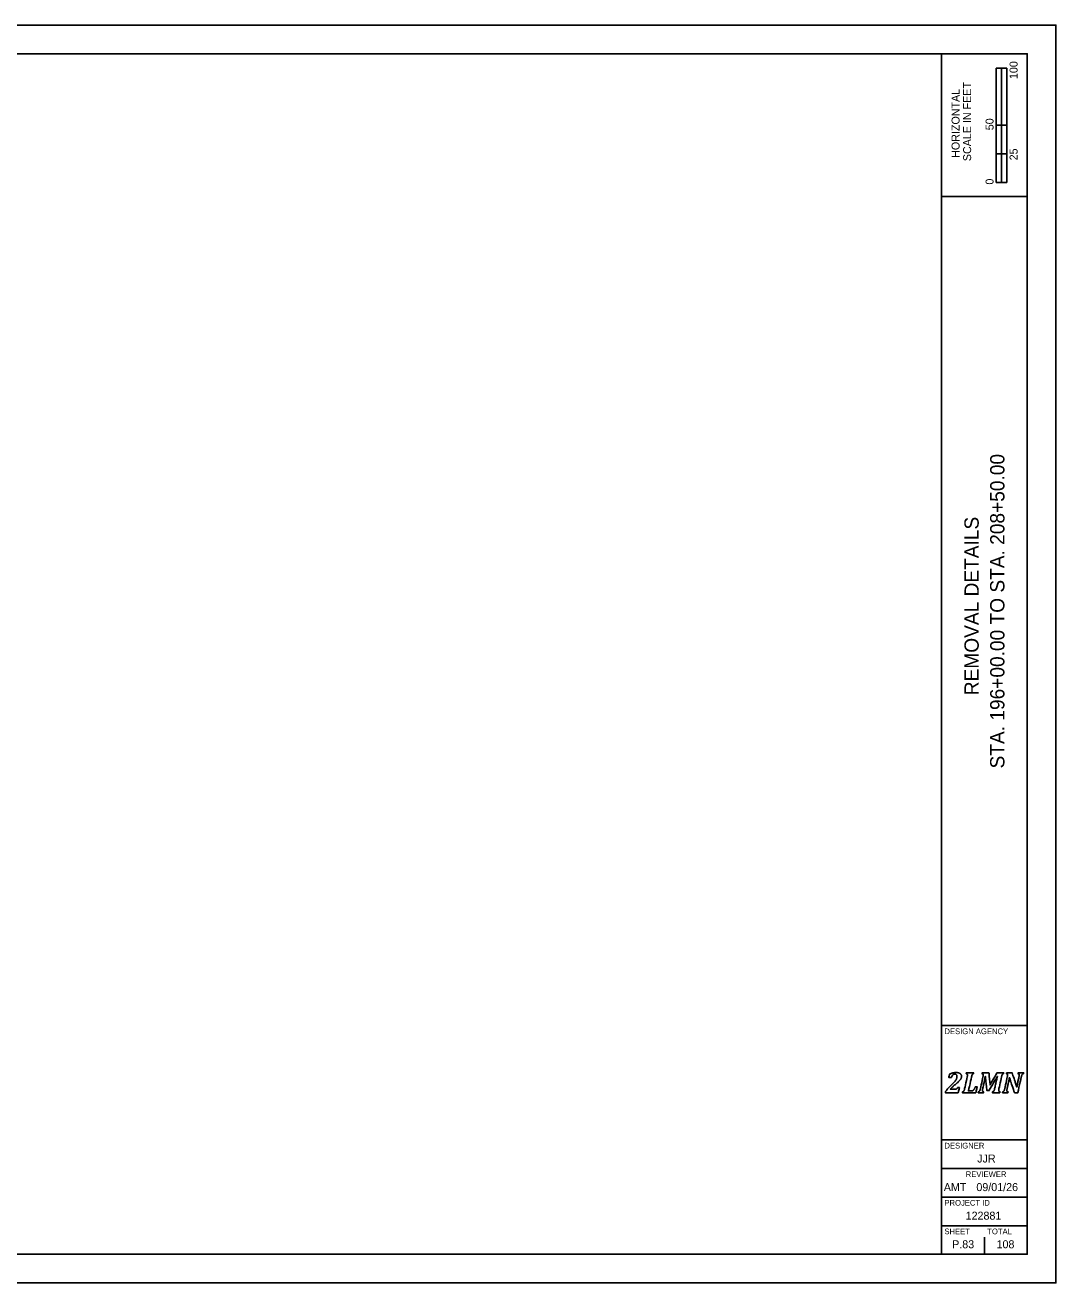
# Model space of a CAD drawing. Extents: x -2.1 to 34, y 0 to 22.
# Drawn here: x 15.96 to 34, y 0 to 22 of the extents above; entities that cross this region are included whole.
import ezdxf

# ---------------------------------------------------------------- set-up
doc = ezdxf.new("R2010")
doc.units = 0
for name, color, linetype in [('SH_Border', 7, 'Continuous'), ('SH_Cut_Line', 7, 'Continuous'), ('SH_Data', 7, 'Continuous')]:
    doc.layers.add(name, color=color, linetype=linetype)

msp = doc.modelspace()

# ---------------------------------------------------------------- linework, layer by layer
at = {"layer": 'SH_Border'}
for p, q in [((32, 0.5), (32, 21.5)), ((32, 19), (33.5, 19)), ((32, 4.5), (33.5, 4.5)), ((32, 2.5), (33.5, 2.5)), ((32, 2), (33.5, 2)), ((32, 1.5), (33.5, 1.5)), ((32, 1), (33.5, 1))]:
    msp.add_line(p, q, dxfattribs=at)
msp.add_lwpolyline([(1.5, 21.5), (33.5, 21.5), (33.5, 0.5), (1.5, 0.5)], close=True, dxfattribs=at)
at = {"layer": 'SH_Cut_Line'}
msp.add_lwpolyline([(0, 0), (34, 0), (34, 22), (0, 22)], close=True, dxfattribs=at)
at = {"layer": 'SH_Data'}
for p, q in [((32.957, 19.25), (32.957, 21.25)), ((33.144, 21.25), (32.957, 21.25)), ((32.957, 20.25), (32.957, 21.25)), ((32.957, 21.25), (33.05, 21.25)), ((33.05, 21.25), (33.051, 21.25)), ((33.051, 21.25), (33.051, 20.25)), ((33.144, 21.25), (33.144, 19.25)), ((33.051, 20.25), (32.957, 20.25)), ((33.143, 20.25), (33.05, 20.25)), ((33.05, 20.25), (33.05, 19.75)), ((33.143, 19.75), (33.143, 20.25)), ((33.05, 19.75), (32.957, 19.75)), ((32.957, 19.75), (32.957, 19.25)), ((33.05, 19.25), (33.05, 19.75)), ((33.05, 19.75), (33.143, 19.75)), ((33.144, 19.25), (32.957, 19.25)), ((32.957, 19.25), (33.05, 19.25)), ((32.75, 3.5), (32.75, 3.5)), ((32.375, 0.675), (32.375, 0.675)), ((32.75, 0.5), (32.75, 0.8))]:
    msp.add_line(p, q, dxfattribs=at)
for points in [[(32.237, 3.388), (32.246, 3.388), (32.253, 3.389), (32.258, 3.39), (32.263, 3.392), (32.267, 3.394), (32.27, 3.397), (32.273, 3.401), (32.277, 3.408), (32.281, 3.417), (32.281, 3.417), (32.312, 3.417), (32.312, 3.417), (32.312, 3.417), (32.29, 3.326), (32.29, 3.326), (32.29, 3.326), (32.066, 3.326), (32.066, 3.326), (32.066, 3.326), (32.069, 3.343), (32.069, 3.343), (32.078, 3.358), (32.091, 3.375), (32.106, 3.394), (32.122, 3.412), (32.144, 3.435), (32.172, 3.462), (32.197, 3.486), (32.217, 3.506), (32.23, 3.521), (32.243, 3.537), (32.253, 3.551), (32.259, 3.566), (32.266, 3.58), (32.269, 3.595), (32.269, 3.61), (32.269, 3.622), (32.266, 3.632), (32.26, 3.64), (32.253, 3.647), (32.245, 3.65), (32.234, 3.65), (32.22, 3.65), (32.208, 3.646), (32.198, 3.636), (32.188, 3.627), (32.18, 3.613), (32.172, 3.593), (32.172, 3.593), (32.126, 3.593), (32.126, 3.593), (32.126, 3.593), (32.14, 3.654), (32.14, 3.654), (32.166, 3.663), (32.188, 3.669), (32.205, 3.673), (32.223, 3.676), (32.24, 3.678), (32.258, 3.678), (32.278, 3.678), (32.295, 3.675), (32.309, 3.669), (32.322, 3.664), (32.332, 3.656), (32.339, 3.646), (32.345, 3.637), (32.348, 3.626), (32.348, 3.613), (32.348, 3.602), (32.346, 3.591), (32.342, 3.581), (32.339, 3.571), (32.333, 3.56), (32.324, 3.549), (32.315, 3.539), (32.304, 3.526), (32.289, 3.513), (32.275, 3.499), (32.254, 3.482), (32.228, 3.46), (32.216, 3.45), (32.202, 3.438), (32.188, 3.425), (32.174, 3.412), (32.162, 3.4), (32.154, 3.391), (32.154, 3.391), (32.153, 3.388), (32.153, 3.388), (32.153, 3.388), (32.237, 3.388), (32.237, 3.388)], [(32.237, 3.388), (32.237, 3.388), (32.153, 3.388), (32.153, 3.388), (32.153, 3.388), (32.154, 3.391), (32.154, 3.391), (32.162, 3.4), (32.174, 3.412), (32.188, 3.425), (32.202, 3.438), (32.216, 3.45), (32.228, 3.46), (32.254, 3.482), (32.275, 3.499), (32.289, 3.513), (32.304, 3.526), (32.315, 3.539), (32.324, 3.549), (32.333, 3.56), (32.339, 3.571), (32.342, 3.581), (32.346, 3.591), (32.348, 3.602), (32.348, 3.613), (32.348, 3.626), (32.345, 3.637), (32.339, 3.646), (32.332, 3.656), (32.322, 3.664), (32.309, 3.669), (32.295, 3.675), (32.278, 3.678), (32.258, 3.678), (32.24, 3.678), (32.223, 3.676), (32.205, 3.673), (32.188, 3.669), (32.166, 3.663), (32.14, 3.654), (32.14, 3.654), (32.126, 3.593), (32.126, 3.593), (32.126, 3.593), (32.172, 3.593), (32.172, 3.593), (32.18, 3.613), (32.188, 3.627), (32.198, 3.636), (32.208, 3.646), (32.22, 3.65), (32.234, 3.65), (32.245, 3.65), (32.253, 3.647), (32.26, 3.64), (32.266, 3.632), (32.269, 3.622), (32.269, 3.61), (32.269, 3.595), (32.266, 3.58), (32.259, 3.566), (32.253, 3.551), (32.243, 3.537), (32.23, 3.521), (32.217, 3.506), (32.197, 3.486), (32.172, 3.462), (32.144, 3.435), (32.122, 3.412), (32.106, 3.394), (32.091, 3.375), (32.078, 3.358), (32.069, 3.343), (32.069, 3.343), (32.066, 3.326), (32.066, 3.326), (32.066, 3.326), (32.29, 3.326), (32.29, 3.326), (32.29, 3.326), (32.312, 3.417), (32.312, 3.417), (32.312, 3.417), (32.281, 3.417), (32.281, 3.417), (32.277, 3.408), (32.273, 3.401), (32.27, 3.397), (32.267, 3.394), (32.263, 3.392), (32.258, 3.39), (32.253, 3.389), (32.246, 3.388), (32.237, 3.388)], [(32.518, 3.356), (32.527, 3.356), (32.533, 3.357), (32.538, 3.358), (32.542, 3.36), (32.546, 3.362), (32.55, 3.365), (32.554, 3.368), (32.558, 3.372), (32.562, 3.377), (32.567, 3.382), (32.571, 3.388), (32.576, 3.397), (32.58, 3.405), (32.585, 3.415), (32.589, 3.427), (32.589, 3.427), (32.624, 3.427), (32.624, 3.427), (32.624, 3.427), (32.598, 3.326), (32.598, 3.326), (32.598, 3.326), (32.365, 3.326), (32.365, 3.326), (32.365, 3.326), (32.369, 3.343), (32.369, 3.343), (32.376, 3.345), (32.381, 3.348), (32.385, 3.351), (32.389, 3.355), (32.392, 3.36), (32.395, 3.366), (32.398, 3.373), (32.4, 3.382), (32.403, 3.395), (32.403, 3.395), (32.449, 3.605), (32.449, 3.605), (32.452, 3.615), (32.453, 3.625), (32.453, 3.635), (32.453, 3.642), (32.451, 3.647), (32.448, 3.651), (32.444, 3.654), (32.439, 3.656), (32.432, 3.657), (32.432, 3.657), (32.435, 3.674), (32.435, 3.674), (32.435, 3.674), (32.563, 3.674), (32.563, 3.674), (32.563, 3.674), (32.559, 3.657), (32.559, 3.657), (32.552, 3.655), (32.547, 3.652), (32.543, 3.649), (32.539, 3.645), (32.536, 3.64), (32.533, 3.634), (32.531, 3.627), (32.528, 3.618), (32.525, 3.605), (32.525, 3.605), (32.47, 3.356), (32.47, 3.356), (32.47, 3.356), (32.518, 3.356), (32.518, 3.356)], [(32.518, 3.356), (32.518, 3.356), (32.47, 3.356), (32.47, 3.356), (32.47, 3.356), (32.525, 3.605), (32.525, 3.605), (32.528, 3.618), (32.531, 3.627), (32.533, 3.634), (32.536, 3.64), (32.539, 3.645), (32.543, 3.649), (32.547, 3.652), (32.552, 3.655), (32.559, 3.657), (32.559, 3.657), (32.563, 3.674), (32.563, 3.674), (32.563, 3.674), (32.435, 3.674), (32.435, 3.674), (32.435, 3.674), (32.432, 3.657), (32.432, 3.657), (32.439, 3.656), (32.444, 3.654), (32.448, 3.651), (32.451, 3.647), (32.453, 3.642), (32.453, 3.635), (32.453, 3.625), (32.452, 3.615), (32.449, 3.605), (32.449, 3.605), (32.403, 3.395), (32.403, 3.395), (32.4, 3.382), (32.398, 3.373), (32.395, 3.366), (32.392, 3.36), (32.389, 3.355), (32.385, 3.351), (32.381, 3.348), (32.376, 3.345), (32.369, 3.343), (32.369, 3.343), (32.365, 3.326), (32.365, 3.326), (32.365, 3.326), (32.598, 3.326), (32.598, 3.326), (32.598, 3.326), (32.624, 3.427), (32.624, 3.427), (32.624, 3.427), (32.589, 3.427), (32.589, 3.427), (32.585, 3.415), (32.58, 3.405), (32.576, 3.397), (32.571, 3.388), (32.567, 3.382), (32.562, 3.377), (32.558, 3.372), (32.554, 3.368), (32.55, 3.365), (32.546, 3.362), (32.542, 3.36), (32.538, 3.358), (32.533, 3.357), (32.527, 3.356), (32.518, 3.356)], [(32.829, 3.674), (32.829, 3.674), (32.849, 3.461), (32.849, 3.461), (32.849, 3.461), (32.969, 3.674), (32.969, 3.674), (32.969, 3.674), (33.087, 3.674), (33.087, 3.674), (33.087, 3.674), (33.084, 3.657), (33.084, 3.657), (33.077, 3.655), (33.071, 3.652), (33.067, 3.649), (33.064, 3.645), (33.06, 3.64), (33.058, 3.634), (33.055, 3.627), (33.052, 3.618), (33.05, 3.605), (33.05, 3.605), (33.003, 3.395), (33.003, 3.395), (33.002, 3.39), (33.002, 3.387), (33.001, 3.384), (33.001, 3.382), (33.001, 3.379), (33, 3.376), (33, 3.373), (33, 3.369), (33, 3.365), (33, 3.358), (33.002, 3.353), (33.005, 3.349), (33.008, 3.346), (33.014, 3.344), (33.021, 3.343), (33.021, 3.343), (33.018, 3.326), (33.018, 3.326), (33.018, 3.326), (32.89, 3.326), (32.89, 3.326), (32.89, 3.326), (32.893, 3.343), (32.893, 3.343), (32.9, 3.345), (32.906, 3.348), (32.91, 3.351), (32.914, 3.355), (32.917, 3.36), (32.919, 3.366), (32.922, 3.373), (32.925, 3.382), (32.928, 3.395), (32.928, 3.395), (32.951, 3.502), (32.951, 3.502), (32.954, 3.513), (32.957, 3.529), (32.962, 3.548), (32.967, 3.568), (32.972, 3.588), (32.978, 3.609), (32.978, 3.609), (32.973, 3.609), (32.973, 3.609), (32.965, 3.594), (32.957, 3.579), (32.948, 3.563), (32.948, 3.563), (32.833, 3.364), (32.833, 3.364), (32.833, 3.364), (32.792, 3.364), (32.792, 3.364), (32.792, 3.364), (32.775, 3.518), (32.775, 3.518), (32.773, 3.537), (32.772, 3.554), (32.77, 3.569), (32.769, 3.583), (32.768, 3.597), (32.768, 3.611), (32.768, 3.611), (32.764, 3.611), (32.764, 3.611), (32.761, 3.596), (32.758, 3.578), (32.755, 3.558), (32.751, 3.538), (32.747, 3.521), (32.744, 3.507), (32.744, 3.507), (32.72, 3.395), (32.72, 3.395), (32.719, 3.39), (32.718, 3.387), (32.718, 3.384), (32.717, 3.382), (32.717, 3.379), (32.717, 3.376), (32.717, 3.373), (32.716, 3.369), (32.716, 3.365), (32.716, 3.358), (32.718, 3.353), (32.721, 3.349), (32.725, 3.346), (32.73, 3.344), (32.738, 3.343), (32.738, 3.343), (32.734, 3.326), (32.734, 3.326), (32.734, 3.326), (32.641, 3.326), (32.641, 3.326), (32.641, 3.326), (32.644, 3.343), (32.644, 3.343), (32.651, 3.345), (32.657, 3.348), (32.661, 3.351), (32.665, 3.355), (32.668, 3.36), (32.67, 3.366), (32.673, 3.373), (32.676, 3.382), (32.679, 3.395), (32.679, 3.395), (32.725, 3.605), (32.725, 3.605), (32.727, 3.615), (32.728, 3.625), (32.728, 3.635), (32.728, 3.642), (32.727, 3.647), (32.723, 3.651), (32.72, 3.654), (32.715, 3.656), (32.707, 3.657), (32.707, 3.657), (32.711, 3.674), (32.711, 3.674), (32.711, 3.674), (32.829, 3.674), (32.829, 3.674)], [(32.829, 3.674), (32.829, 3.674), (32.711, 3.674), (32.711, 3.674), (32.711, 3.674), (32.707, 3.657), (32.707, 3.657), (32.715, 3.656), (32.72, 3.654), (32.723, 3.651), (32.727, 3.647), (32.728, 3.642), (32.728, 3.635), (32.728, 3.625), (32.727, 3.615), (32.725, 3.605), (32.725, 3.605), (32.679, 3.395), (32.679, 3.395), (32.676, 3.382), (32.673, 3.373), (32.67, 3.366), (32.668, 3.36), (32.665, 3.355), (32.661, 3.351), (32.657, 3.348), (32.651, 3.345), (32.644, 3.343), (32.644, 3.343), (32.641, 3.326), (32.641, 3.326), (32.641, 3.326), (32.734, 3.326), (32.734, 3.326), (32.734, 3.326), (32.738, 3.343), (32.738, 3.343), (32.73, 3.344), (32.725, 3.346), (32.721, 3.349), (32.718, 3.353), (32.716, 3.358), (32.716, 3.365), (32.716, 3.369), (32.717, 3.373), (32.717, 3.376), (32.717, 3.379), (32.717, 3.382), (32.718, 3.384), (32.718, 3.387), (32.719, 3.39), (32.72, 3.395), (32.72, 3.395), (32.744, 3.507), (32.744, 3.507), (32.747, 3.521), (32.751, 3.538), (32.755, 3.558), (32.758, 3.578), (32.761, 3.596), (32.764, 3.611), (32.764, 3.611), (32.768, 3.611), (32.768, 3.611), (32.768, 3.597), (32.769, 3.583), (32.77, 3.569), (32.772, 3.554), (32.773, 3.537), (32.775, 3.518), (32.775, 3.518), (32.792, 3.364), (32.792, 3.364), (32.792, 3.364), (32.833, 3.364), (32.833, 3.364), (32.833, 3.364), (32.948, 3.563), (32.948, 3.563), (32.957, 3.579), (32.965, 3.594), (32.973, 3.609), (32.973, 3.609), (32.978, 3.609), (32.978, 3.609), (32.972, 3.588), (32.967, 3.568), (32.962, 3.548), (32.957, 3.529), (32.954, 3.513), (32.951, 3.502), (32.951, 3.502), (32.928, 3.395), (32.928, 3.395), (32.925, 3.382), (32.922, 3.373), (32.919, 3.366), (32.917, 3.36), (32.914, 3.355), (32.91, 3.351), (32.906, 3.348), (32.9, 3.345), (32.893, 3.343), (32.893, 3.343), (32.89, 3.326), (32.89, 3.326), (32.89, 3.326), (33.018, 3.326), (33.018, 3.326), (33.018, 3.326), (33.021, 3.343), (33.021, 3.343), (33.014, 3.344), (33.008, 3.346), (33.005, 3.349), (33.002, 3.353), (33, 3.358), (33, 3.365), (33, 3.369), (33, 3.373), (33, 3.376), (33.001, 3.379), (33.001, 3.382), (33.001, 3.384), (33.002, 3.387), (33.002, 3.39), (33.003, 3.395), (33.003, 3.395), (33.05, 3.605), (33.05, 3.605), (33.052, 3.618), (33.055, 3.627), (33.058, 3.634), (33.06, 3.64), (33.064, 3.645), (33.067, 3.649), (33.071, 3.652), (33.077, 3.655), (33.084, 3.657), (33.084, 3.657), (33.087, 3.674), (33.087, 3.674), (33.087, 3.674), (32.969, 3.674), (32.969, 3.674), (32.969, 3.674), (32.849, 3.461), (32.849, 3.461), (32.849, 3.461), (32.829, 3.674), (32.829, 3.674)], [(33.137, 3.674), (33.137, 3.674), (33.234, 3.674), (33.234, 3.674), (33.234, 3.674), (33.283, 3.53), (33.283, 3.53), (33.296, 3.49), (33.307, 3.456), (33.315, 3.426), (33.315, 3.426), (33.318, 3.426), (33.318, 3.426), (33.323, 3.455), (33.329, 3.488), (33.337, 3.523), (33.337, 3.523), (33.355, 3.605), (33.355, 3.605), (33.357, 3.615), (33.358, 3.625), (33.358, 3.635), (33.358, 3.642), (33.357, 3.647), (33.353, 3.651), (33.35, 3.654), (33.345, 3.656), (33.337, 3.657), (33.337, 3.657), (33.341, 3.674), (33.341, 3.674), (33.341, 3.674), (33.434, 3.674), (33.434, 3.674), (33.434, 3.674), (33.431, 3.657), (33.431, 3.657), (33.424, 3.655), (33.418, 3.652), (33.414, 3.649), (33.41, 3.645), (33.407, 3.64), (33.405, 3.634), (33.402, 3.627), (33.399, 3.618), (33.396, 3.605), (33.396, 3.605), (33.335, 3.326), (33.335, 3.326), (33.335, 3.326), (33.277, 3.326), (33.277, 3.326), (33.277, 3.326), (33.216, 3.504), (33.216, 3.504), (33.211, 3.518), (33.207, 3.531), (33.204, 3.543), (33.2, 3.556), (33.195, 3.571), (33.19, 3.59), (33.19, 3.59), (33.186, 3.59), (33.186, 3.59), (33.185, 3.579), (33.182, 3.563), (33.179, 3.543), (33.175, 3.523), (33.17, 3.501), (33.165, 3.478), (33.165, 3.478), (33.147, 3.395), (33.147, 3.395), (33.146, 3.39), (33.145, 3.387), (33.145, 3.384), (33.144, 3.382), (33.144, 3.379), (33.144, 3.376), (33.143, 3.373), (33.143, 3.369), (33.143, 3.365), (33.143, 3.358), (33.145, 3.353), (33.148, 3.349), (33.152, 3.346), (33.157, 3.344), (33.164, 3.343), (33.164, 3.343), (33.161, 3.326), (33.161, 3.326), (33.161, 3.326), (33.067, 3.326), (33.067, 3.326), (33.067, 3.326), (33.071, 3.343), (33.071, 3.343), (33.078, 3.345), (33.083, 3.348), (33.087, 3.351), (33.091, 3.355), (33.094, 3.36), (33.097, 3.366), (33.1, 3.373), (33.102, 3.382), (33.105, 3.395), (33.105, 3.395), (33.151, 3.605), (33.151, 3.605), (33.154, 3.615), (33.155, 3.625), (33.155, 3.635), (33.155, 3.642), (33.153, 3.647), (33.15, 3.651), (33.146, 3.654), (33.141, 3.656), (33.134, 3.657), (33.134, 3.657), (33.137, 3.674), (33.137, 3.674)], [(33.137, 3.674), (33.137, 3.674), (33.134, 3.657), (33.134, 3.657), (33.141, 3.656), (33.146, 3.654), (33.15, 3.651), (33.153, 3.647), (33.155, 3.642), (33.155, 3.635), (33.155, 3.625), (33.154, 3.615), (33.151, 3.605), (33.151, 3.605), (33.105, 3.395), (33.105, 3.395), (33.102, 3.382), (33.1, 3.373), (33.097, 3.366), (33.094, 3.36), (33.091, 3.355), (33.087, 3.351), (33.083, 3.348), (33.078, 3.345), (33.071, 3.343), (33.071, 3.343), (33.067, 3.326), (33.067, 3.326), (33.067, 3.326), (33.161, 3.326), (33.161, 3.326), (33.161, 3.326), (33.164, 3.343), (33.164, 3.343), (33.157, 3.344), (33.152, 3.346), (33.148, 3.349), (33.145, 3.353), (33.143, 3.358), (33.143, 3.365), (33.143, 3.369), (33.143, 3.373), (33.144, 3.376), (33.144, 3.379), (33.144, 3.382), (33.145, 3.384), (33.145, 3.387), (33.146, 3.39), (33.147, 3.395), (33.147, 3.395), (33.165, 3.478), (33.165, 3.478), (33.17, 3.501), (33.175, 3.523), (33.179, 3.543), (33.182, 3.563), (33.185, 3.579), (33.186, 3.59), (33.186, 3.59), (33.19, 3.59), (33.19, 3.59), (33.195, 3.571), (33.2, 3.556), (33.204, 3.543), (33.207, 3.531), (33.211, 3.518), (33.216, 3.504), (33.216, 3.504), (33.277, 3.326), (33.277, 3.326), (33.277, 3.326), (33.335, 3.326), (33.335, 3.326), (33.335, 3.326), (33.396, 3.605), (33.396, 3.605), (33.399, 3.618), (33.402, 3.627), (33.405, 3.634), (33.407, 3.64), (33.41, 3.645), (33.414, 3.649), (33.418, 3.652), (33.424, 3.655), (33.431, 3.657), (33.431, 3.657), (33.434, 3.674), (33.434, 3.674), (33.434, 3.674), (33.341, 3.674), (33.341, 3.674), (33.341, 3.674), (33.337, 3.657), (33.337, 3.657), (33.345, 3.656), (33.35, 3.654), (33.353, 3.651), (33.357, 3.647), (33.358, 3.642), (33.358, 3.635), (33.358, 3.625), (33.357, 3.615), (33.355, 3.605), (33.355, 3.605), (33.337, 3.523), (33.337, 3.523), (33.329, 3.488), (33.323, 3.455), (33.318, 3.426), (33.318, 3.426), (33.315, 3.426), (33.315, 3.426), (33.307, 3.456), (33.296, 3.49), (33.283, 3.53), (33.283, 3.53), (33.234, 3.674), (33.234, 3.674), (33.234, 3.674), (33.137, 3.674), (33.137, 3.674)]]:
    msp.add_open_spline(points, degree=3, dxfattribs=at)

# ---------------------------------------------------------------- texts
for s, height, p in [('100', 0.14, (33.33, 21.057)), ('SCALE IN FEET', 0.14, (32.517, 19.621)), ('HORIZONTAL', 0.14, (32.315, 19.679)), ('50', 0.14, (32.91, 20.162)), ('25', 0.14, (33.33, 19.635)), ('0', 0.14, (32.91, 19.211)), ('STA. 196+00.00 TO STA. 208+50.00', 0.25, (33.1, 8.998)), ('REMOVAL DETAILS', 0.25, (32.65, 10.279))]:
    msp.add_text(s, height=height, rotation=90, dxfattribs=at).set_placement(p)
for s, height, p in [('DESIGN AGENCY', 0.1, (32.05, 4.35)), ('DESIGNER', 0.1, (32.05, 2.35)), ('JJR', 0.14, (32.624, 2.105)), ('REVIEWER', 0.1, (32.422, 1.85)), ('AMT', 0.14, (32.039, 1.605)), ('09/01/26', 0.14, (32.609, 1.605)), ('PROJECT ID', 0.1, (32.05, 1.35)), ('122881', 0.14, (32.421, 1.105)), ('SHEET', 0.1, (32.05, 0.85)), ('TOTAL', 0.1, (32.8, 0.85)), ('P.83', 0.14, (32.185, 0.605)), ('108', 0.14, (32.962, 0.605))]:
    msp.add_text(s, height=height, dxfattribs=at).set_placement(p)

doc.saveas('drawing.dxf')
